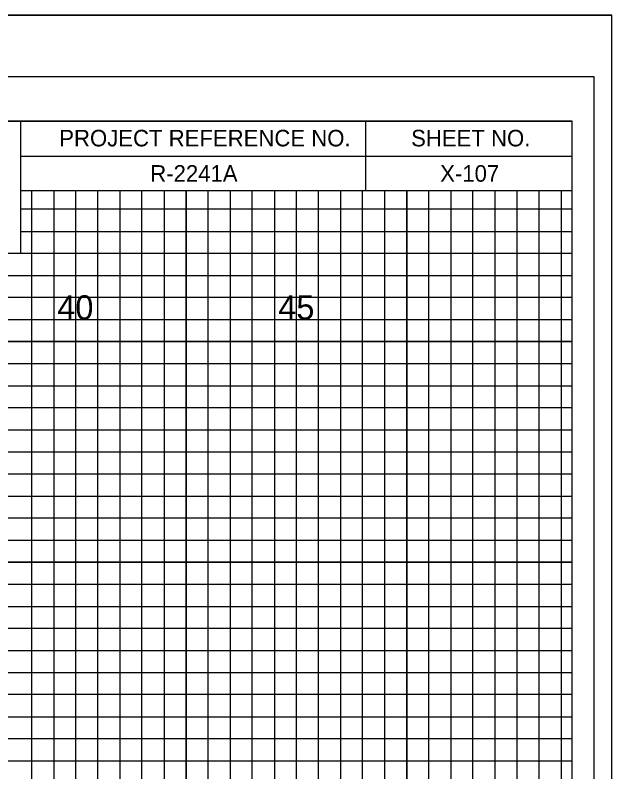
# Model space of a CAD drawing. Extents: x -4 to 103, y -2 to 351.
# Drawn here: x 89.88 to 103.4, y 333.55 to 350.7 of the extents above; entities that cross this region are included whole.
import ezdxf

# ---------------------------------------------------------------- set-up
doc = ezdxf.new("R2010")
doc.units = 0
for name, color, linetype in [('Old_Level_10', 7, 'Continuous'), ('Old_Level_16', 7, 'Continuous'), ('Old_Level_3', 7, 'Continuous'), ('Old_Level_4', 7, 'Continuous'), ('Old_Level_5', 7, 'Continuous'), ('Old_Level_6', 7, 'Continuous'), ('Old_Level_8', 7, 'Continuous'), ('Prop Dimension', 7, 'Continuous'), ('Prop Terminator CELL', 7, 'Continuous'), ('Prop XS SE Text', 7, 'Continuous')]:
    doc.layers.add(name, color=color, linetype=linetype)

msp = doc.modelspace()

# ---------------------------------------------------------------- linework, layer by layer
at = {"layer": 'Old_Level_10'}
for p, q in [((91.25, 283.3), (91.25, 346.725)), ((93.75, 283.3), (93.75, 346.725)), ((96.25, 283.3), (96.25, 346.725)), ((98.75, 283.3), (98.75, 346.725)), ((101.25, 283.3), (101.25, 346.725)), ((90, 345.8), (102.5, 345.8)), ((0, 343.3), (102.5, 343.3)), ((0, 340.8), (102.5, 340.8)), ((0, 338.3), (102.5, 338.3)), ((0, 335.8), (102.5, 335.8))]:
    msp.add_line(p, q, dxfattribs=at)
at = {"layer": 'Old_Level_3'}
msp.add_line((-3.5, 350.7), (103.4, 350.7), dxfattribs=at)
at = {"layer": 'Old_Level_4'}
for points in [[(90.25, 283.3), (90.25, 346.725), (90.75, 346.725), (90.75, 283.3)], [(91.75, 283.3), (91.75, 346.725), (92.25, 346.725), (92.25, 283.3)], [(92.75, 283.3), (92.75, 346.725), (93.25, 346.725), (93.25, 283.3)], [(94.25, 283.3), (94.25, 346.725), (94.75, 346.725), (94.75, 283.3)], [(95.25, 283.3), (95.25, 346.725), (95.75, 346.725), (95.75, 283.3)], [(96.75, 283.3), (96.75, 346.725), (97.25, 346.725), (97.25, 283.3)], [(97.75, 283.3), (97.75, 346.725), (98.25, 346.725), (98.25, 283.3)], [(99.25, 283.3), (99.25, 346.725), (99.75, 346.725), (99.75, 283.3)], [(100.25, 283.3), (100.25, 346.725)], [(100.25, 346.725), (100.75, 346.725), (100.75, 283.3), (101.75, 283.3), (101.75, 346.725), (102.25, 346.725), (102.25, 283.3)], [(102.5, 345.3), (102.5, 346.3), (90, 346.3)], [(0, 344.8), (102.5, 344.8), (102.5, 345.3), (0, 345.3)], [(0, 343.8), (102.5, 343.8), (102.5, 344.3), (0, 344.3)], [(0, 342.3), (102.5, 342.3), (102.5, 342.8), (0, 342.8)], [(0, 341.3), (102.5, 341.3), (102.5, 341.8), (0, 341.8)], [(0, 339.8), (102.5, 339.8), (102.5, 340.3), (0, 340.3)], [(0, 338.8), (102.5, 338.8), (102.5, 339.3), (0, 339.3)], [(0, 337.3), (102.5, 337.3), (102.5, 337.8), (0, 337.8)], [(0, 336.3), (102.5, 336.3), (102.5, 336.8), (0, 336.8)], [(0, 334.8), (102.5, 334.8), (102.5, 335.3), (0, 335.3)], [(0, 333.8), (102.5, 333.8), (102.5, 334.3), (0, 334.3)]]:
    msp.add_lwpolyline(points, dxfattribs=at)
at = {"layer": 'Old_Level_5'}
msp.add_lwpolyline([(103.4, 350.7), (-3.5, 350.7), (-3.5, 280.875), (103.4, 280.875)], close=True, dxfattribs=at)
at = {"layer": 'Old_Level_6'}
for p, q in [((90, 348.3), (102.5, 348.3)), ((90, 348.3), (102.5, 348.3)), ((97.825, 346.725), (97.825, 348.3)), ((101.875, 348.3), (101.875, 348.3)), ((102.5, 348.3), (102.5, 348.3)), ((102.5, 346.725), (102.5, 348.3)), ((102.5, 348.3), (102.5, 348.3)), ((102.5, 348.3), (102.5, 348.3)), ((102.5, 346.725), (102.5, 348.3)), ((90, 347.5), (102.5, 347.5)), ((90, 346.725), (102.5, 346.725)), ((99.4, 346.725), (99.4, 346.725)), ((99.4, 346.725), (99.4, 346.725))]:
    msp.add_line(p, q, dxfattribs=at)
for points in [[(102.5, 348.3), (0, 348.3), (0, 283.3), (102.5, 283.3)], [(83.75, 348.3), (90, 348.3), (90, 345.3), (83.75, 345.3)]]:
    msp.add_lwpolyline(points, close=True, dxfattribs=at)
at = {"layer": 'Old_Level_8'}
for points in [[(91.25, 283.3), (91.25, 346.725), (93.75, 346.725), (93.75, 283.3)], [(96.25, 283.3), (96.25, 346.725), (98.75, 346.725), (98.75, 283.3)], [(101.25, 283.3), (101.25, 346.725)], [(90, 345.8), (102.5, 345.8)], [(0, 340.8), (102.5, 340.8), (102.5, 343.3), (0, 343.3)], [(0, 335.8), (102.5, 335.8), (102.5, 338.3), (0, 338.3)]]:
    msp.add_lwpolyline(points, dxfattribs=at)
at = {"layer": 'Prop XS SE Text'}
msp.add_lwpolyline([(103, 349.3), (-2.8, 349.3), (-2.8, 282.3), (103, 282.3)], close=True, dxfattribs=at)

# ---------------------------------------------------------------- texts
at = {"layer": 'Old_Level_16'}
for s, p in [('40', (90.8313, 343.8)), ('45', (95.8399, 343.8))]:
    msp.add_text(s, height=0.55, dxfattribs=at).set_placement(p)
at = {"layer": 'Old_Level_6'}
for s, p in [('PROJECT REFERENCE NO.', (90.875, 347.725)), ('SHEET NO.', (98.85, 347.725))]:
    msp.add_text(s, height=0.375, dxfattribs=at).set_placement(p)
at = {"layer": 'Prop Dimension'}
msp.add_text('X-107', height=0.375, dxfattribs=at).set_placement((99.5089, 346.925))
at = {"layer": 'Prop Terminator CELL'}
msp.add_text('R-2241A', height=0.375, dxfattribs=at).set_placement((92.9378, 346.925))

doc.saveas('drawing.dxf')
